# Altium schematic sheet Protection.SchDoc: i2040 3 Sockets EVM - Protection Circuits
size 431 x 279 mm; Date: Not shown in title block; ApprovedBy: Not shown in title block; CheckedBy: Not shown in title block; Author: Not shown in title block; CompanyName: Texas Instruments; DrawnBy: Mars Leung; Engineer: Mars Leung; Organization: Not shown in title block; Address1: Not shown in title block; Address2: Not shown in title block; Address3: Not shown in title block; Address4: Not shown in title block; DocumentNumber: 1; Revision: Use project parameter SCH_Rev; SheetNumber: 3; SheetTotal: 3; PageSetup: Record=PageOptions|CenterHorizontal=True|CenterVertical=True|PrintScale=1.00|XCorrection=1.00|YCorrection=1.00|PrintKind=0|BorderSize=5000000|LeftOffset=0|BottomOffset=0|Orientation=2|PaperLength=1000|PaperWidth=1000|Scale=100|PaperSource=15|PrintQuality=600|MediaType=1|DitherType=10|PaperKind=Letter|PrintScaleMode=1
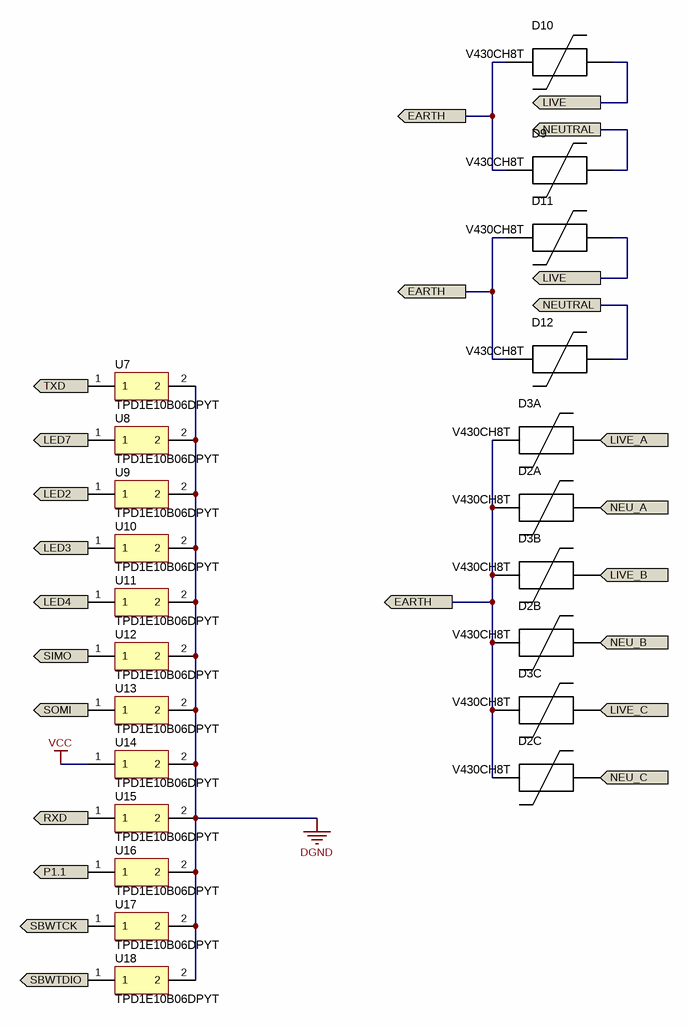
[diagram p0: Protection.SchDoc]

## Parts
D2A  V430CH8T  [V430CH8T]
D2B  V430CH8T  [V430CH8T]
D2C  V430CH8T  [V430CH8T]
D3A  V430CH8T  [V430CH8T]
D3B  V430CH8T  [V430CH8T]
D3C  V430CH8T  [V430CH8T]
D9  V430CH8T  [V430CH8T]
D10  V430CH8T  [V430CH8T]
D11  V430CH8T  [V430CH8T]
D12  V430CH8T  [V430CH8T]
U7  TPD1E10B06DPYT  [DPY0002A_N]
U8  TPD1E10B06DPYT  [DPY0002A_N]
U9  TPD1E10B06DPYT  [DPY0002A_N]
U10  TPD1E10B06DPYT  [DPY0002A_N]
U11  TPD1E10B06DPYT  [DPY0002A_N]
U12  TPD1E10B06DPYT  [DPY0002A_N]
U13  TPD1E10B06DPYT  [DPY0002A_N]
U14  TPD1E10B06DPYT  [DPY0002A_N]
U15  TPD1E10B06DPYT  [DPY0002A_N]
U16  TPD1E10B06DPYT  [DPY0002A_N]
U17  TPD1E10B06DPYT  [DPY0002A_N]
U18  TPD1E10B06DPYT  [DPY0002A_N]

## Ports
EARTH, LED2, LED3, LED4, LED7, LIVE, LIVE_A, LIVE_B, LIVE_C, NEU_A, NEU_B, NEU_C, NEUTRAL, P1.1, RXD, SBWTCK, SBWTDIO, SIMO, SOMI, TXD

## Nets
DGND: U7.2 U8.2 U9.2 U10.2 U11.2 U12.2 U13.2 U14.2 U15.2 U16.2 U17.2 U18.2
VCC: U14.1
EARTH: D2A.1 D2B.1 D2C.1 D3A.1 D3B.1 D3C.1 D9.1 D10.1 D11.1 D12.2 ; port EARTH
LED2: U9.1 ; port LED2
LED3: U10.1 ; port LED3
LED4: U11.1 ; port LED4
LED7: U8.1 ; port LED7
LIVE: D10.2 D11.2 ; port LIVE
LIVE_A: D3A.2 ; port LIVE_A
LIVE_B: D3B.2 ; port LIVE_B
LIVE_C: D3C.2 ; port LIVE_C
NEU_A: D2A.2 ; port NEU_A
NEU_B: D2B.2 ; port NEU_B
NEU_C: D2C.2 ; port NEU_C
NEUTRAL: D9.2 D12.1 ; port NEUTRAL
P1.1: U16.1 ; port P1.1
RXD: U15.1 ; port RXD
SBWTCK: U17.1 ; port SBWTCK
SBWTDIO: U18.1 ; port SBWTDIO
SIMO: U12.1 ; port SIMO
SOMI: U13.1 ; port SOMI
TXD: U7.1 ; port TXD

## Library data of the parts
D2A D2B D2C D3A D3B D3C D9-D12 = V430CH8T: VARISTOR 389V 250A 2-SMD; Manufacturer: Used in BOM report; SymbolVersion: use current date i.e. 2008-05-20; SymbolCreator: Use a-id; CompType: Used in some BOM reports.  Useful for finding later.; U/M: EA, IN, or GM; Number of Circuits: 1; Maximum AC Volts: 275VAC; Maximum DC Volts: 369VDC; Energy: 8.0J
U7-U18 = TPD1E10B06DPYT: ESD Protection in 0402 Package with 10 pF Capacitance and 6 V Breakdown, 1 Channel, -40 to +125 degC, 2-pin X2SON (DPY); Manufacturer: Texas Instruments; Alternate Manufacturer: None; Alternate PartNumber: Equivalent; Breakdown Voltage(Min)(V): 6; Eco-Plan: TBD; IEC 61000-4-2 Air-Gap(+/- kV): 30; IO Capacitance(Typ)(pF): 10; SubFamily: ESD Solution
